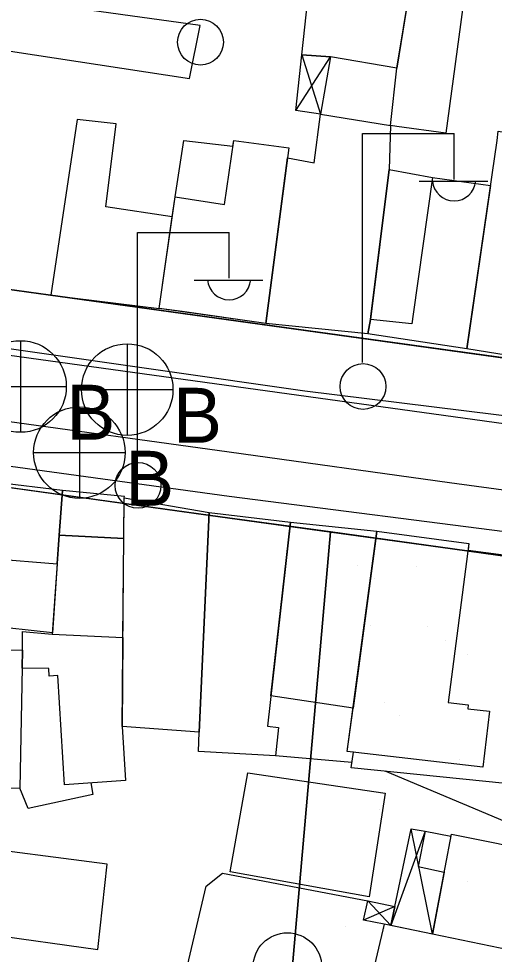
# Model space of a CAD drawing. Extents: x 417997 to 421451, y 4451742 to 4455216.
# Drawn here: x 419867.9 to 419904.2, y 4452298.1 to 4452369.6 of the extents above; entities that cross this region are included whole.
import ezdxf

# ---------------------------------------------------------------- set-up
doc = ezdxf.new("R2010")
doc.units = 0
for name, color, linetype in [('ADA', 7, 'Continuous'), ('ADAKENARI', 7, 'Continuous'), ('B_Ins_Halinde', 7, 'Continuous'), ('B_Mesken', 7, 'Continuous'), ('B_Sundurma', 7, 'Continuous'), ('B_Teras', 7, 'Continuous'), ('Default', 7, 'Continuous'), ('KALDIRIM', 7, 'Continuous'), ('PL_AYA_PARK_DINLENME', 7, 'Continuous'), ('PL_T_TURIZM_TA', 7, 'Continuous'), ('PL_TİCK', 7, 'Continuous'), ('S_Elektrik_Diregi', 7, 'Continuous'), ('S_Rogar_Kapagi_Buski', 7, 'Continuous'), ('S_Tek_Agac', 7, 'Continuous'), ('Sinir_Duvar_tek_tarafa_ait', 7, 'Continuous'), ('TR_PARKALANI', 7, 'Continuous'), ('TR_TİCK', 7, 'Continuous'), ('Yol_Sose', 7, 'Continuous')]:
    doc.layers.add(name, color=color, linetype=linetype)

# ---------------------------------------------------------------- blocks, each defined once
blk = doc.blocks.new('POINT_DISPLAY')
at = {"layer": 'Default'}
blk.add_line((0, 0), (0, 0), dxfattribs=at)

msp = doc.modelspace()

# ---------------------------------------------------------------- linework, layer by layer
at = {"layer": 'ADA'}
msp.add_line((419891.699, 4452330.38), (419883.582, 4452237.595), dxfattribs=at)
msp.add_line((419891.699, 4452330.38), (419883.582, 4452237.595), dxfattribs=at)
at = {"layer": 'ADAKENARI'}
for p, q in [((419905.991, 4452343.547), (419824.841, 4452354.764)), ((419905.991, 4452343.547), (419824.841, 4452354.764)), ((419820.707, 4452340.193), (419883.275, 4452331.544)), ((419820.707, 4452340.193), (419883.275, 4452331.544)), ((419883.275, 4452331.544), (419900.124, 4452329.216)), ((419883.275, 4452331.544), (419900.124, 4452329.216)), ((419900.124, 4452329.216), (419905.43, 4452328.482)), ((419900.124, 4452329.216), (419905.43, 4452328.482))]:
    msp.add_line(p, q, dxfattribs=at)
at = {"layer": 'B_Ins_Halinde'}
msp.add_lwpolyline([(419858.738, 4452305.798), (419857.988, 4452302.524), (419862.044, 4452301.63), (419861.456, 4452298.883), (419865.252, 4452298.133), (419865.49, 4452299.633), (419873.924, 4452298.463), (419874.615, 4452304.975), (419863.215, 4452306.467), (419863.012, 4452305.337)], close=True, dxfattribs=at)
at = {"layer": 'B_Mesken'}
for points in [[(419890.796, 4452378.616), (419898.731, 4452377.799), (419896.784, 4452365.825), (419891.7, 4452366.684), (419889.527, 4452366.86)], [(419897.767, 4452371.865), (419898.731, 4452377.799), (419902.747, 4452377.27), (419901.964, 4452371.449), (419900.539, 4452360.855), (419896.776, 4452361.377), (419896.298, 4452361.453), (419896.784, 4452365.825), (419897.767, 4452371.865)], [(419888.417, 4452358.97), (419890.465, 4452358.582), (419890.947, 4452362.306), (419896.298, 4452361.453), (419896.204, 4452358.078), (419894.761, 4452346.631), (419894.555, 4452345.521), (419886.762, 4452346.321)], [(419910.535, 4452343.018), (419902.132, 4452344.369), (419904.447, 4452360.313), (419904.525, 4452361.01), (419912.442, 4452359.654), (419912.386, 4452359.382)], [(419880.501, 4452360.305), (419884.243, 4452359.868), (419884.305, 4452360.295), (419888.517, 4452359.73), (419886.762, 4452346.321), (419878.597, 4452347.468), (419879.592, 4452354.47), (419879.829, 4452355.989)], [(419899.511, 4452357.481), (419903.946, 4452356.858), (419902.132, 4452344.369), (419894.555, 4452345.521), (419894.761, 4452346.631), (419896.204, 4452358.078)], [(419865.749, 4452328.354), (419870.801, 4452327.943), (419870.952, 4452330.139), (419871.21, 4452333.54), (419866.103, 4452334.152)], [(419870.952, 4452330.139), (419875.906, 4452329.885), (419875.936, 4452332.989), (419875.943, 4452333.089), (419871.21, 4452333.54)], [(419875.768, 4452315.516), (419875.936, 4452332.989), (419882.425, 4452331.858), (419881.652, 4452315.064)], [(419881.652, 4452315.064), (419882.425, 4452331.858), (419888.64, 4452331.117), (419886.895, 4452315.543), (419887.729, 4452315.429), (419887.495, 4452313.254), (419881.614, 4452313.605), (419881.652, 4452315.064)], [(419888.64, 4452331.117), (419895.253, 4452330.434), (419893.439, 4452316.917), (419887.152, 4452317.841)], [(419870.431, 4452322.565), (419875.834, 4452322.316), (419875.906, 4452329.885), (419870.952, 4452330.139)], [(419902.229, 4452328.995), (419909.954, 4452327.976), (419906.845, 4452310.981), (419893.287, 4452312.348), (419893.466, 4452313.54), (419892.993, 4452313.594), (419893.439, 4452316.917), (419895.253, 4452330.434), (419902.295, 4452329.502)], [(419865.284, 4452323.219), (419865.749, 4452328.354), (419870.801, 4452327.943), (419870.438, 4452322.662)], [(419867.942, 4452310.787), (419862.556, 4452310.696), (419859.951, 4452310.714), (419860.189, 4452322.345), (419860.219, 4452323.831), (419863.585, 4452323.548), (419863.537, 4452322.107), (419864.824, 4452322.09), (419864.824, 4452321.425), (419868.146, 4452321.332)], [(419875.768, 4452315.516), (419876.035, 4452311.39), (419871.36, 4452311.043), (419870.863, 4452319.394), (419870.195, 4452319.346), (419870.161, 4452319.94), (419868.12, 4452319.972), (419868.146, 4452321.332), (419868.161, 4452322.776), (419870.431, 4452322.565), (419875.834, 4452322.316), (419875.768, 4452315.516)], [(419885.39, 4452311.969), (419895.9, 4452310.412), (419894.664, 4452302.497), (419884.028, 4452304.387)], [(419906.164, 4452298.259), (419899.5, 4452299.644), (419900.951, 4452307.29), (419908.191, 4452305.819), (419906.485, 4452298.177)], [(419893.991, 4452292.719), (419904.277, 4452290.582), (419906.164, 4452298.259), (419895.816, 4452300.409)]]:
    msp.add_lwpolyline(points, close=True, dxfattribs=at)
at = {"layer": 'B_Sundurma'}
for p, q in [((419889.067, 4452362.599), (419891.7, 4452366.684)), ((419889.527, 4452366.86), (419890.947, 4452362.306)), ((419898.942, 4452307.499), (419896.319, 4452300.305)), ((419899.5, 4452299.644), (419897.881, 4452307.697)), ((419896.623, 4452301.74), (419894.242, 4452300.703)), ((419894.573, 4452302.176), (419896.319, 4452300.305))]:
    msp.add_line(p, q, dxfattribs=at)
for points in [[(419889.067, 4452362.599), (419889.527, 4452366.86), (419891.7, 4452366.684), (419890.947, 4452362.306)], [(419898.942, 4452307.499), (419898.42, 4452304.802), (419900.398, 4452304.377), (419899.5, 4452299.644), (419896.319, 4452300.305), (419897.881, 4452307.697)], [(419894.573, 4452302.176), (419896.623, 4452301.74), (419896.319, 4452300.305), (419895.816, 4452300.409), (419894.242, 4452300.703)]]:
    msp.add_lwpolyline(points, close=True, dxfattribs=at)
at = {"layer": 'B_Teras'}
for points in [[(419896.298, 4452361.453), (419896.784, 4452365.825), (419897.767, 4452371.865), (419901.964, 4452371.449), (419900.539, 4452360.855), (419896.776, 4452361.377)], [(419872.338, 4452361.904), (419870.324, 4452348.488), (419878.597, 4452347.468), (419879.592, 4452354.47), (419874.522, 4452355.228), (419875.311, 4452361.587)], [(419880.37, 4452347.219), (419878.597, 4452347.468), (419879.829, 4452355.989), (419883.598, 4452355.418), (419884.305, 4452360.295), (419888.517, 4452359.73), (419886.87, 4452347.15), (419886.762, 4452346.321)], [(419894.816, 4452347.066), (419896.204, 4452358.078), (419899.511, 4452357.481), (419898.031, 4452347.031), (419897.925, 4452346.285), (419894.761, 4452346.631)], [(419892.993, 4452313.594), (419895.253, 4452330.434), (419902.295, 4452329.502), (419900.699, 4452317.332), (419902.245, 4452317.152), (419902.216, 4452316.871), (419903.877, 4452316.673), (419903.348, 4452312.403)]]:
    msp.add_lwpolyline(points, close=True, dxfattribs=at)
at = {"layer": 'KALDIRIM'}
for p, q in [((419912.449, 4452337.607), (419817.422, 4452350.742)), ((419912.449, 4452337.607), (419817.422, 4452350.742)), ((419815.869, 4452345.909), (419883.96, 4452336.497)), ((419815.869, 4452345.909), (419883.96, 4452336.497)), ((419883.96, 4452336.497), (419900.808, 4452334.168)), ((419883.96, 4452336.497), (419900.808, 4452334.168)), ((419900.808, 4452334.168), (419912.718, 4452332.522)), ((419900.808, 4452334.168), (419912.718, 4452332.522))]:
    msp.add_line(p, q, dxfattribs=at)
at = {"layer": 'PL_AYA_PARK_DINLENME'}
msp.add_lwpolyline([(419912.903, 4452271.898), (419912.105, 4452278.403), (419909.984, 4452309.653), (419910.197, 4452322.801), (419905.43, 4452328.482), (419900.124, 4452329.216), (419891.699, 4452330.38), (419886.662, 4452272.805), (419912.903, 4452271.898)], dxfattribs=at)
msp.add_lwpolyline([(419912.903, 4452271.898), (419912.105, 4452278.403), (419909.984, 4452309.653), (419910.197, 4452322.801), (419905.43, 4452328.482), (419900.124, 4452329.216), (419891.699, 4452330.38), (419886.662, 4452272.805), (419912.903, 4452271.898)], dxfattribs=at)
at = {"layer": 'PL_T_TURIZM_TA'}
msp.add_lwpolyline([(419883.582, 4452237.595), (419886.662, 4452272.805), (419891.699, 4452330.38), (419883.275, 4452331.544), (419820.707, 4452340.193), (419810.074, 4452331.589), (419807.203, 4452292.199), (419805.532, 4452282.386), (419793.654, 4452238.545)], dxfattribs=at)
msp.add_lwpolyline([(419883.582, 4452237.595), (419886.662, 4452272.805), (419891.699, 4452330.38), (419883.275, 4452331.544), (419820.707, 4452340.193), (419810.074, 4452331.589), (419807.203, 4452292.199), (419805.532, 4452282.386), (419793.654, 4452238.545)], dxfattribs=at)
at = {"layer": 'PL_TİCK'}
msp.add_lwpolyline([(419845.37, 4452436.166), (419842.015, 4452427.344), (419818.489, 4452365.48), (419824.841, 4452354.764), (419905.991, 4452343.547), (419911.13, 4452347.859), (419915.721, 4452471.309), (419916.056, 4452480.305), (419851.01, 4452485.028)], dxfattribs=at)
msp.add_lwpolyline([(419845.37, 4452436.166), (419842.015, 4452427.344), (419818.489, 4452365.48), (419824.841, 4452354.764), (419905.991, 4452343.547), (419911.13, 4452347.859), (419915.721, 4452471.309), (419916.056, 4452480.305), (419851.01, 4452485.028)], dxfattribs=at)
at = {"layer": 'S_Elektrik_Diregi'}
for p, q in [((419894.159, 4452343.331), (419894.159, 4452360.831)), ((419894.159, 4452360.831), (419901.159, 4452360.831)), ((419901.159, 4452357.331), (419901.159, 4452360.831)), ((419898.499, 4452357.191), (419903.749, 4452357.191)), ((419876.952, 4452335.771), (419876.952, 4452353.271)), ((419876.952, 4452353.271), (419883.952, 4452353.271)), ((419883.952, 4452349.771), (419883.952, 4452353.271)), ((419881.292, 4452349.631), (419886.542, 4452349.631))]:
    msp.add_line(p, q, dxfattribs=at)
for centre in [(419881.763, 4452367.818), (419894.195, 4452341.496), (419876.988, 4452333.936)]:
    msp.add_circle(centre, 1.75, dxfattribs=at)
for centre in [(419901.159, 4452357.344), (419883.953, 4452349.784)]:
    msp.add_arc(centre, 1.658, 184.83843, 355.14641, dxfattribs=at)
at = {"layer": 'S_Rogar_Kapagi_Buski'}
for p, q in [((419868.002, 4452344.996), (419868.002, 4452337.996)), ((419876.16, 4452344.761), (419876.16, 4452337.761)), ((419864.502, 4452341.496), (419871.502, 4452341.496)), ((419872.66, 4452341.261), (419879.66, 4452341.261)), ((419872.502, 4452339.946), (419872.502, 4452332.946)), ((419869.002, 4452336.446), (419876.002, 4452336.446))]:
    msp.add_line(p, q, dxfattribs=at)
for centre in [(419868.002, 4452341.496), (419876.16, 4452341.261), (419872.502, 4452336.446)]:
    msp.add_circle(centre, 3.5, dxfattribs=at)
at = {"layer": 'S_Tek_Agac'}
msp.add_circle((419888.415, 4452297.113), 2.625, dxfattribs=at)
at = {"layer": 'Sinir_Duvar_tek_tarafa_ait'}
for points in [[(419893.349, 4452312.76), (419887.495, 4452313.254)], [(419905.048, 4452308.236), (419895.887, 4452312.086)], [(419873.39, 4452311.194), (419873.53, 4452310.318), (419868.587, 4452309.238), (419867.942, 4452310.787)], [(419898.942, 4452307.499), (419900.919, 4452307.122)], [(419879.479, 4452291.705), (419882.206, 4452303.295), (419883.452, 4452304.291), (419894.573, 4452302.176)]]:
    msp.add_lwpolyline(points, dxfattribs=at)
at = {"layer": 'TR_TİCK'}
msp.add_lwpolyline([(419845.37, 4452436.166), (419842.015, 4452427.344), (419818.489, 4452365.48), (419824.841, 4452354.764), (419905.991, 4452343.547), (419911.13, 4452347.859), (419915.721, 4452471.309), (419916.056, 4452480.305)], dxfattribs=at)
msp.add_lwpolyline([(419845.37, 4452436.166), (419842.015, 4452427.344), (419818.489, 4452365.48), (419824.841, 4452354.764), (419905.991, 4452343.547), (419911.13, 4452347.859), (419915.721, 4452471.309), (419916.056, 4452480.305)], dxfattribs=at)
at = {"layer": 'Yol_Sose'}
for points in [[(419830.485, 4452349.257), (419802.868, 4452352.587), (419802.213, 4452352.896), (419801.879, 4452353.313), (419801.551, 4452354.005), (419803.43, 4452368.314), (419804.928, 4452375.795), (419805.294, 4452376.437), (419805.88, 4452376.7), (419823.603, 4452374.276), (419848.351, 4452369.998), (419880.936, 4452365.044), (419881.737, 4452369.101), (419856.612, 4452372.591), (419819.071, 4452378.937), (419807.415, 4452380.842), (419807.073, 4452381.354), (419807.103, 4452381.969), (419809.4, 4452404.935), (419809.855, 4452407.01), (419811.747, 4452409.056)], [(419945.3, 4452346.531), (419944.233, 4452338.864), (419943.147, 4452336.216), (419942.696, 4452335.609), (419942.224, 4452335.309), (419940.909, 4452334.728), (419939.591, 4452334.605), (419916.737, 4452337.808), (419889.754, 4452341.15), (419857.319, 4452345.766), (419843.122, 4452347.613)], [(419809.894, 4452324.456), (419809.511, 4452333.873), (419809.68, 4452339.915), (419809.686, 4452340.142), (419809.787, 4452340.531), (419809.882, 4452340.852), (419810.085, 4452341.18), (419810.338, 4452341.471), (419810.594, 4452341.675), (419811.097, 4452342.005), (419811.654, 4452342.298), (419812.285, 4452342.532), (419812.678, 4452342.61), (419814.449, 4452342.5), (419825.198, 4452341.415), (419845.542, 4452338.324), (419865.163, 4452335.678), (419883.953, 4452333.102), (419907.017, 4452330.165)]]:
    msp.add_lwpolyline(points, dxfattribs=at)

# ---------------------------------------------------------------- block references
at = {"layer": 'TR_PARKALANI', "xscale": 0.1, "yscale": 0.10000000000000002}
for p in [(419893.8, 4452327.817), (419893.8, 4452327.817), (419898.316, 4452327.773), (419898.316, 4452327.773), (419895.107, 4452326.806), (419895.107, 4452326.806), (419894.803, 4452323.256), (419894.803, 4452323.256), (419899.159, 4452323.117), (419899.159, 4452323.117), (419900.466, 4452322.105), (419900.466, 4452322.105), (419902.212, 4452320.99), (419902.212, 4452320.99), (419895.865, 4452317.338), (419895.865, 4452317.338), (419896.956, 4452316.362), (419896.956, 4452316.362), (419901.572, 4452313.009), (419901.572, 4452313.009), (419896.016, 4452311.473), (419896.016, 4452311.473), (419895.489, 4452309.136), (419895.489, 4452309.136), (419900.466, 4452304.806), (419900.466, 4452304.806), (419889.99, 4452303.691), (419889.99, 4452303.691), (419902.212, 4452303.691), (419902.212, 4452303.691), (419892.863, 4452300.226), (419892.863, 4452300.226), (419895.865, 4452300.039), (419895.865, 4452300.039)]:
    msp.add_blockref('POINT_DISPLAY', p, dxfattribs=at)

# ---------------------------------------------------------------- texts
at = {"layer": 'S_Rogar_Kapagi_Buski'}
for p in [(419871.502, 4452337.432), (419879.66, 4452337.196), (419876.002, 4452332.382)]:
    msp.add_text('B', height=4.2, dxfattribs=at).set_placement(p)

doc.saveas('drawing.dxf')
